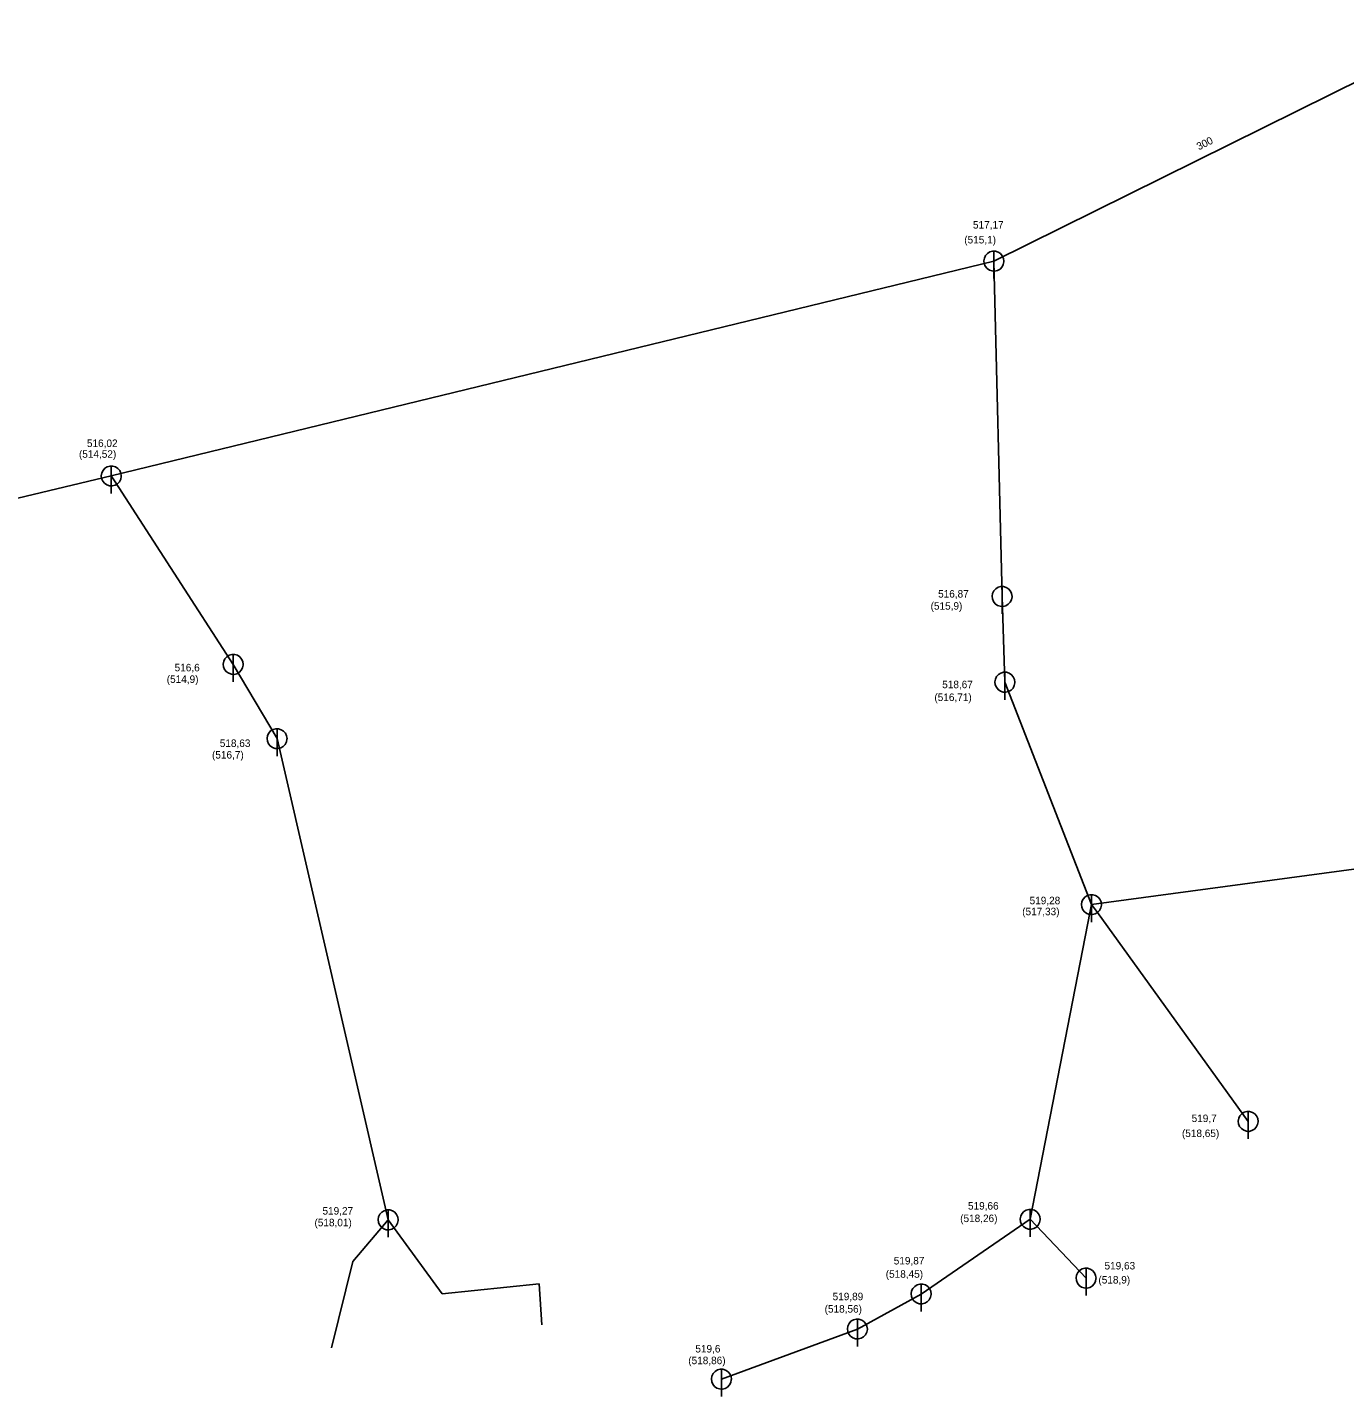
# Model space of a CAD drawing. Extents: x -476058 to -471893, y -1155786 to -1152000.
# Drawn here: x -474266.6 to -474134.8, y -1154059.5 to -1153922.4 of the extents above; entities that cross this region are included whole.
import ezdxf

# ---------------------------------------------------------------- set-up
doc = ezdxf.new("R2010")
doc.units = 0
for name, color, linetype in [('Vrstva 10', 7, 'Continuous'), ('Vrstva 18', 7, 'Continuous'), ('Vrstva 3', 7, 'Continuous'), ('Vrstva 4', 7, 'Continuous'), ('Vrstva 45', 7, 'Continuous'), ('Vrstva 50', 7, 'Continuous'), ('Vrstva 51', 7, 'Continuous')]:
    doc.layers.add(name, color=color, linetype=linetype)

msp = doc.modelspace()

# ---------------------------------------------------------------- linework, layer by layer
at = {"layer": 'Vrstva 10'}
for p, q in [((-474169.87, -1153944.83), (-474169.87, -1153947.58)), ((-474258.22, -1153966.33), (-474258.22, -1153969.08)), ((-474169.05, -1153978.38), (-474169.05, -1153981.13)), ((-474246.02, -1153985.19), (-474246.02, -1153987.94)), ((-474168.76, -1153986.97), (-474168.76, -1153989.72)), ((-474241.63, -1153992.62), (-474241.63, -1153995.37)), ((-474160.1, -1154009.23), (-474160.1, -1154011.98)), ((-474144.41, -1154030.92), (-474144.41, -1154033.67)), ((-474230.5, -1154040.78), (-474230.5, -1154043.52)), ((-474166.23, -1154040.72), (-474166.23, -1154043.47)), ((-474160.64, -1154046.61), (-474160.64, -1154049.36)), ((-474177.14, -1154048.2), (-474177.14, -1154050.95)), ((-474183.53, -1154051.7), (-474183.53, -1154054.45)), ((-474197.14, -1154056.72), (-474197.14, -1154059.47))]:
    msp.add_line(p, q, dxfattribs=at)
for points in [[(-474168.87, -1153945.83), (-474168.91, -1153945.55), (-474169.02, -1153945.29), (-474169.21, -1153945.08), (-474169.44, -1153944.93), (-474169.71, -1153944.84), (-474169.99, -1153944.84), (-474170.27, -1153944.91), (-474170.51, -1153945.06), (-474170.7, -1153945.27), (-474170.82, -1153945.53), (-474170.87, -1153945.8), (-474170.84, -1153946.08), (-474170.73, -1153946.34), (-474170.55, -1153946.56), (-474170.32, -1153946.73), (-474170.05, -1153946.81), (-474169.77, -1153946.83), (-474169.49, -1153946.76), (-474169.25, -1153946.62), (-474169.05, -1153946.41), (-474168.92, -1153946.16), (-474168.87, -1153945.89), (-474168.87, -1153945.83)], [(-474257.22, -1153967.33), (-474257.26, -1153967.05), (-474257.38, -1153966.79), (-474257.56, -1153966.58), (-474257.8, -1153966.42), (-474258.07, -1153966.34), (-474258.35, -1153966.34), (-474258.62, -1153966.41), (-474258.86, -1153966.56), (-474259.05, -1153966.77), (-474259.17, -1153967.02), (-474259.22, -1153967.3), (-474259.19, -1153967.58), (-474259.08, -1153967.84), (-474258.9, -1153968.06), (-474258.67, -1153968.22), (-474258.41, -1153968.31), (-474258.12, -1153968.32), (-474257.85, -1153968.26), (-474257.6, -1153968.12), (-474257.41, -1153967.91), (-474257.28, -1153967.66), (-474257.22, -1153967.39), (-474257.22, -1153967.33)], [(-474168.05, -1153979.38), (-474168.09, -1153979.1), (-474168.2, -1153978.85), (-474168.39, -1153978.63), (-474168.62, -1153978.48), (-474168.89, -1153978.39), (-474169.17, -1153978.39), (-474169.45, -1153978.47), (-474169.68, -1153978.61), (-474169.88, -1153978.82), (-474170, -1153979.08), (-474170.05, -1153979.35), (-474170.01, -1153979.64), (-474169.91, -1153979.9), (-474169.73, -1153980.11), (-474169.5, -1153980.28), (-474169.23, -1153980.37), (-474168.95, -1153980.38), (-474168.67, -1153980.31), (-474168.43, -1153980.17), (-474168.23, -1153979.97), (-474168.1, -1153979.72), (-474168.05, -1153979.44), (-474168.05, -1153979.38)], [(-474245.02, -1153986.19), (-474245.06, -1153985.91), (-474245.17, -1153985.65), (-474245.36, -1153985.44), (-474245.59, -1153985.28), (-474245.86, -1153985.2), (-474246.15, -1153985.2), (-474246.42, -1153985.27), (-474246.66, -1153985.42), (-474246.85, -1153985.63), (-474246.97, -1153985.88), (-474247.02, -1153986.16), (-474246.99, -1153986.44), (-474246.88, -1153986.7), (-474246.7, -1153986.92), (-474246.47, -1153987.08), (-474246.2, -1153987.17), (-474245.92, -1153987.19), (-474245.65, -1153987.12), (-474245.4, -1153986.98), (-474245.21, -1153986.77), (-474245.08, -1153986.52), (-474245.02, -1153986.25), (-474245.02, -1153986.19)], [(-474167.76, -1153987.97), (-474167.8, -1153987.69), (-474167.92, -1153987.43), (-474168.1, -1153987.22), (-474168.33, -1153987.06), (-474168.6, -1153986.98), (-474168.89, -1153986.98), (-474169.16, -1153987.05), (-474169.4, -1153987.2), (-474169.59, -1153987.41), (-474169.71, -1153987.66), (-474169.76, -1153987.94), (-474169.73, -1153988.22), (-474169.62, -1153988.48), (-474169.44, -1153988.7), (-474169.21, -1153988.86), (-474168.94, -1153988.95), (-474168.66, -1153988.96), (-474168.39, -1153988.9), (-474168.14, -1153988.76), (-474167.95, -1153988.55), (-474167.82, -1153988.3), (-474167.76, -1153988.02), (-474167.76, -1153987.97)], [(-474240.63, -1153993.62), (-474240.67, -1153993.34), (-474240.79, -1153993.08), (-474240.97, -1153992.87), (-474241.21, -1153992.72), (-474241.48, -1153992.63), (-474241.76, -1153992.63), (-474242.03, -1153992.7), (-474242.27, -1153992.85), (-474242.46, -1153993.06), (-474242.59, -1153993.31), (-474242.63, -1153993.59), (-474242.6, -1153993.87), (-474242.49, -1153994.13), (-474242.32, -1153994.35), (-474242.08, -1153994.52), (-474241.82, -1153994.6), (-474241.53, -1153994.62), (-474241.26, -1153994.55), (-474241.02, -1153994.41), (-474240.82, -1153994.2), (-474240.69, -1153993.95), (-474240.64, -1153993.68), (-474240.63, -1153993.62)], [(-474159.1, -1154010.23), (-474159.14, -1154009.95), (-474159.26, -1154009.69), (-474159.44, -1154009.48), (-474159.68, -1154009.32), (-474159.95, -1154009.24), (-474160.23, -1154009.24), (-474160.5, -1154009.31), (-474160.74, -1154009.46), (-474160.93, -1154009.67), (-474161.05, -1154009.92), (-474161.1, -1154010.2), (-474161.07, -1154010.48), (-474160.96, -1154010.74), (-474160.78, -1154010.96), (-474160.55, -1154011.12), (-474160.28, -1154011.21), (-474160, -1154011.23), (-474159.73, -1154011.16), (-474159.48, -1154011.02), (-474159.29, -1154010.81), (-474159.16, -1154010.56), (-474159.1, -1154010.29), (-474159.1, -1154010.23)], [(-474143.41, -1154031.92), (-474143.45, -1154031.64), (-474143.57, -1154031.38), (-474143.75, -1154031.17), (-474143.98, -1154031.02), (-474144.26, -1154030.93), (-474144.54, -1154030.93), (-474144.81, -1154031), (-474145.05, -1154031.15), (-474145.24, -1154031.36), (-474145.36, -1154031.61), (-474145.41, -1154031.89), (-474145.38, -1154032.17), (-474145.27, -1154032.43), (-474145.09, -1154032.65), (-474144.86, -1154032.81), (-474144.59, -1154032.9), (-474144.31, -1154032.92), (-474144.04, -1154032.85), (-474143.79, -1154032.71), (-474143.6, -1154032.5), (-474143.47, -1154032.25), (-474143.41, -1154031.98), (-474143.41, -1154031.92)], [(-474229.5, -1154041.78), (-474229.54, -1154041.5), (-474229.66, -1154041.24), (-474229.84, -1154041.02), (-474230.08, -1154040.87), (-474230.35, -1154040.79), (-474230.63, -1154040.78), (-474230.9, -1154040.86), (-474231.14, -1154041.01), (-474231.33, -1154041.22), (-474231.46, -1154041.47), (-474231.5, -1154041.75), (-474231.47, -1154042.03), (-474231.36, -1154042.29), (-474231.18, -1154042.51), (-474230.95, -1154042.67), (-474230.69, -1154042.76), (-474230.4, -1154042.77), (-474230.13, -1154042.7), (-474229.89, -1154042.56), (-474229.69, -1154042.36), (-474229.56, -1154042.11), (-474229.51, -1154041.83), (-474229.5, -1154041.78)], [(-474165.23, -1154041.72), (-474165.27, -1154041.44), (-474165.39, -1154041.18), (-474165.57, -1154040.97), (-474165.81, -1154040.81), (-474166.08, -1154040.73), (-474166.36, -1154040.73), (-474166.63, -1154040.8), (-474166.87, -1154040.95), (-474167.06, -1154041.16), (-474167.18, -1154041.41), (-474167.23, -1154041.69), (-474167.2, -1154041.97), (-474167.09, -1154042.23), (-474166.91, -1154042.45), (-474166.68, -1154042.61), (-474166.41, -1154042.7), (-474166.13, -1154042.71), (-474165.86, -1154042.65), (-474165.61, -1154042.5), (-474165.42, -1154042.3), (-474165.29, -1154042.05), (-474165.23, -1154041.77), (-474165.23, -1154041.72)], [(-474159.64, -1154047.61), (-474159.68, -1154047.33), (-474159.8, -1154047.07), (-474159.98, -1154046.86), (-474160.22, -1154046.7), (-474160.49, -1154046.62), (-474160.77, -1154046.62), (-474161.04, -1154046.69), (-474161.28, -1154046.84), (-474161.47, -1154047.05), (-474161.6, -1154047.3), (-474161.64, -1154047.58), (-474161.61, -1154047.86), (-474161.5, -1154048.12), (-474161.33, -1154048.34), (-474161.09, -1154048.5), (-474160.83, -1154048.59), (-474160.54, -1154048.6), (-474160.27, -1154048.54), (-474160.03, -1154048.4), (-474159.83, -1154048.19), (-474159.7, -1154047.94), (-474159.65, -1154047.66), (-474159.64, -1154047.61)], [(-474176.14, -1154049.2), (-474176.18, -1154048.92), (-474176.3, -1154048.66), (-474176.48, -1154048.45), (-474176.72, -1154048.29), (-474176.99, -1154048.21), (-474177.27, -1154048.21), (-474177.54, -1154048.28), (-474177.78, -1154048.43), (-474177.97, -1154048.64), (-474178.1, -1154048.89), (-474178.14, -1154049.17), (-474178.11, -1154049.45), (-474178, -1154049.71), (-474177.83, -1154049.93), (-474177.59, -1154050.09), (-474177.33, -1154050.18), (-474177.04, -1154050.19), (-474176.77, -1154050.13), (-474176.53, -1154049.99), (-474176.33, -1154049.78), (-474176.2, -1154049.53), (-474176.15, -1154049.25), (-474176.14, -1154049.2)], [(-474182.53, -1154052.7), (-474182.57, -1154052.42), (-474182.68, -1154052.17), (-474182.87, -1154051.95), (-474183.1, -1154051.8), (-474183.37, -1154051.71), (-474183.65, -1154051.71), (-474183.93, -1154051.78), (-474184.17, -1154051.93), (-474184.36, -1154052.14), (-474184.48, -1154052.4), (-474184.53, -1154052.67), (-474184.49, -1154052.95), (-474184.39, -1154053.21), (-474184.21, -1154053.43), (-474183.98, -1154053.59), (-474183.71, -1154053.69), (-474183.43, -1154053.7), (-474183.15, -1154053.63), (-474182.91, -1154053.49), (-474182.71, -1154053.28), (-474182.58, -1154053.03), (-474182.53, -1154052.76), (-474182.53, -1154052.7)], [(-474196.14, -1154057.72), (-474196.18, -1154057.44), (-474196.3, -1154057.18), (-474196.48, -1154056.97), (-474196.72, -1154056.81), (-474196.99, -1154056.73), (-474197.27, -1154056.73), (-474197.54, -1154056.8), (-474197.78, -1154056.95), (-474197.97, -1154057.16), (-474198.1, -1154057.41), (-474198.14, -1154057.69), (-474198.11, -1154057.97), (-474198, -1154058.23), (-474197.83, -1154058.45), (-474197.59, -1154058.61), (-474197.33, -1154058.7), (-474197.04, -1154058.71), (-474196.77, -1154058.65), (-474196.53, -1154058.51), (-474196.33, -1154058.3), (-474196.2, -1154058.05), (-474196.15, -1154057.77), (-474196.14, -1154057.72)]]:
    msp.add_lwpolyline(points, dxfattribs=at)
at = {"layer": 'Vrstva 45'}
for points in [[(-474122.62, -1153922.44), (-474169.87, -1153945.83)], [(-474169.87, -1153945.83), (-474258.22, -1153967.33)], [(-474169.05, -1153979.38), (-474169.87, -1153945.83)], [(-474258.22, -1153967.33), (-474343.2, -1153987.63)], [(-474168.76, -1153987.97), (-474169.05, -1153979.38)], [(-474160.1, -1154010.23), (-474168.76, -1153987.97)], [(-474128.64, -1154005.99), (-474160.1, -1154010.23)]]:
    msp.add_lwpolyline(points, dxfattribs=at)
at = {"layer": 'Vrstva 50'}
for points in [[(-474257.85, -1153967.91), (-474258.22, -1153967.33)], [(-474246.02, -1153986.19), (-474257.85, -1153967.91)], [(-474241.63, -1153993.62), (-474246.02, -1153986.19)], [(-474230.5, -1154041.78), (-474241.63, -1153993.62)], [(-474160.23, -1154010.9), (-474160.1, -1154010.23)], [(-474159.5, -1154011.01), (-474160.1, -1154010.23)], [(-474166.23, -1154041.72), (-474160.23, -1154010.9)], [(-474159.5, -1154011.01), (-474144.41, -1154031.92)], [(-474230.5, -1154041.78), (-474234.05, -1154045.96), (-474236.19, -1154054.6)], [(-474177.14, -1154049.2), (-474166.23, -1154041.72)], [(-474197.14, -1154057.72), (-474183.53, -1154052.7), (-474177.14, -1154049.2)]]:
    msp.add_lwpolyline(points, dxfattribs=at)
at = {"layer": 'Vrstva 51'}
for points in [[(-474230.5, -1154041.78), (-474225.09, -1154049.18), (-474215.39, -1154048.18), (-474215.11, -1154052.28)], [(-474166.23, -1154041.72), (-474160.64, -1154047.61)]]:
    msp.add_lwpolyline(points, dxfattribs=at)

# ---------------------------------------------------------------- texts
at = {"layer": 'Vrstva 18'}
msp.add_text('300 ', height=0.75, rotation=26.3425, dxfattribs=at).set_placement((-474149.35, -1153934.75))
at = {"layer": 'Vrstva 3'}
for s, p in [('517,17', (-474171.96, -1153942.57)), ('516,02', (-474260.66, -1153964.43)), ('516,87', (-474175.45, -1153979.5)), ('516,6', (-474251.88, -1153986.88)), ('518,67', (-474175.04, -1153988.57)), ('518,63', (-474247.36, -1153994.45)), ('519,28', (-474166.29, -1154010.19)), ('519,7', (-474150.07, -1154031.99)), ('519,66', (-474172.46, -1154040.75)), ('519,27', (-474237.08, -1154041.25)), ('519,87', (-474179.89, -1154046.24)), ('519,63', (-474158.79, -1154046.74)), ('519,89', (-474186.01, -1154049.82)), ('519,6', (-474199.75, -1154055.05))]:
    msp.add_text(s, height=0.75, dxfattribs=at).set_placement(p)
at = {"layer": 'Vrstva 4'}
for s, p in [('(515,1)', (-474172.83, -1153944.06)), ('(514,52)', (-474261.46, -1153965.51)), ('(515,9)', (-474176.2, -1153980.71)), ('(514,9)', (-474252.67, -1153988.04)), ('(516,71)', (-474175.82, -1153989.85)), ('(516,7)', (-474248.14, -1153995.61)), ('(517,33)', (-474167.03, -1154011.29)), ('(518,65)', (-474151.04, -1154033.49)), ('(518,01)', (-474237.88, -1154042.42)), ('(518,26)', (-474173.24, -1154042)), ('(518,45)', (-474180.69, -1154047.57)), ('(518,9)', (-474159.4, -1154048.15)), ('(518,56)', (-474186.81, -1154051.06)), ('(518,86)', (-474200.46, -1154056.22))]:
    msp.add_text(s, height=0.75, dxfattribs=at).set_placement(p)

doc.saveas('drawing.dxf')
